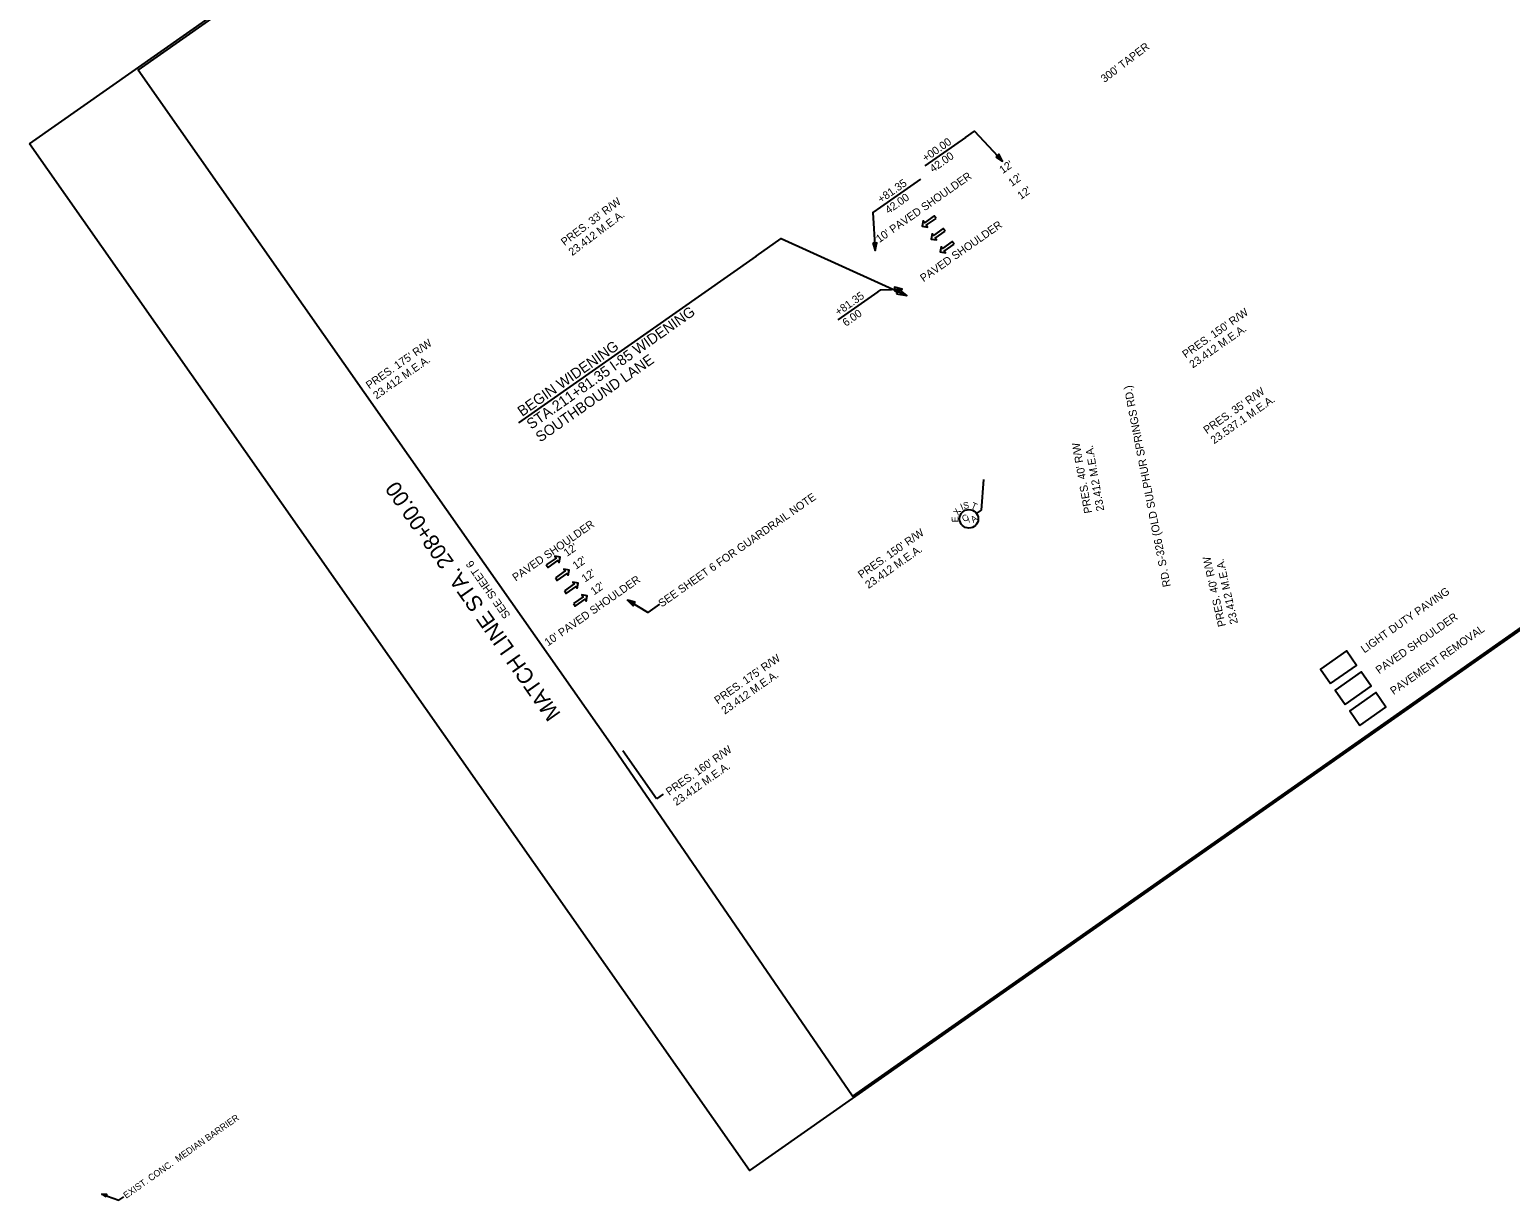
# Model space of a CAD drawing. Extents: x 1603735 to 1605655, y 1088656 to 1090462.
# Drawn here: x 1603735 to 1604864, y 1088656 to 1089549 of the extents above; entities that cross this region are included whole.
import ezdxf

# ---------------------------------------------------------------- set-up
doc = ezdxf.new("R2010")
doc.units = 0
for name, color, linetype in [('Copy of RD_HC_SUR_Bearing_TX200', 7, 'Continuous'), ('RD_DTM_BkLn1', 7, 'Continuous'), ('RD_EX_BldgApp', 7, 'Continuous'), ('RD_EX_Fence_Other', 7, 'Continuous'), ('RD_EX_Misc', 7, 'Continuous'), ('RD_EX_Misc_Golf_Teebox', 7, 'Continuous'), ('RD_EX_UT', 7, 'Continuous'), ('RD_EX_VEG', 7, 'Continuous'), ('RD_HC_SUR_CL400', 7, 'Continuous'), ('TR_PM_Yellow_Solid', 7, 'Continuous')]:
    doc.layers.add(name, color=color, linetype=linetype)

msp = doc.modelspace()

# ---------------------------------------------------------------- linework, layer by layer
at = {"layer": 'Copy of RD_HC_SUR_Bearing_TX200'}
msp.add_lwpolyline([(1604215.3, 1089110.4), (1604206.4, 1089104.2), (1604190.9, 1089113.5)], dxfattribs=at)
msp.add_lwpolyline([(1604196.7, 1089111.9), (1604190.9, 1089113.5), (1604195.1, 1089109.2)], close=True, dxfattribs=at)
at = {"layer": 'RD_DTM_BkLn1'}
msp.add_lwpolyline([(1603793, 1088658.5), (1603793.7, 1088660.2), (1603789.9, 1088660.6)], close=True, dxfattribs=at)
msp.add_lwpolyline([(1603789.9, 1088660.6), (1603802.9, 1088655.8), (1603806.7, 1088658.5)], dxfattribs=at)
at = {"layer": 'RD_EX_BldgApp'}
for p, q in [((1604213, 1088962), (1604187.4, 1088998.6)), ((1604218.1, 1088965.5), (1604213, 1088962))]:
    msp.add_line(p, q, dxfattribs=at)
at = {"layer": 'RD_EX_Fence_Other'}
msp.add_lwpolyline([(1603734.7, 1089461.6), (1605106, 1090423.5), (1605655.3, 1089640.4), (1604284, 1088678.5)], close=True, dxfattribs=at)
at = {"layer": 'RD_EX_Misc'}
for points in [[(1604426.2, 1089404.7), (1604424.8, 1089406.7), (1604417.3, 1089401.4), (1604416.4, 1089402.8), (1604415.7, 1089398.8), (1604419.6, 1089398.1), (1604418.7, 1089399.5)], [(1604433.1, 1089394.9), (1604431.7, 1089396.9), (1604424.2, 1089391.6), (1604423.3, 1089392.9), (1604422.6, 1089389), (1604426.5, 1089388.3), (1604425.6, 1089389.6)], [(1604440, 1089385.1), (1604438.6, 1089387), (1604431.1, 1089381.8), (1604430.1, 1089383.1), (1604429.5, 1089379.2), (1604433.4, 1089378.5), (1604432.5, 1089379.8)], [(1604128.9, 1089140.4), (1604130.3, 1089138.4), (1604137.8, 1089143.7), (1604138.7, 1089142.3), (1604139.4, 1089146.3), (1604135.5, 1089147), (1604136.4, 1089145.6)], [(1604135.8, 1089130.5), (1604137.2, 1089128.6), (1604144.7, 1089133.8), (1604145.6, 1089132.5), (1604146.3, 1089136.4), (1604142.4, 1089137.1), (1604143.3, 1089135.8)], [(1604142.7, 1089120.7), (1604144.1, 1089118.7), (1604151.6, 1089124), (1604152.5, 1089122.7), (1604153.2, 1089126.6), (1604149.2, 1089127.3), (1604150.2, 1089126)], [(1604149.6, 1089110.9), (1604150.9, 1089108.9), (1604158.5, 1089114.2), (1604159.4, 1089112.9), (1604160.1, 1089116.8), (1604156.1, 1089117.5), (1604157.1, 1089116.2)]]:
    msp.add_lwpolyline(points, close=True, dxfattribs=at)
at = {"layer": 'RD_EX_Misc_Golf_Teebox'}
for p, q in [((1604448.7, 1089466.5), (1604417.8, 1089444.9)), ((1604414.3, 1089434.7), (1604383.8, 1089413.3)), ((1604288.9, 1089376), (1604107.6, 1089248.8)), ((1604381.8, 1089348.8), (1604351.3, 1089327.4))]:
    msp.add_line(p, q, dxfattribs=at)
for points in [[(1604448.7, 1089466.5), (1604455.5, 1089471.3), (1604476.9, 1089448.4)], [(1604383.8, 1089413.3), (1604378.1, 1089409.3), (1604379.8, 1089380.2)], [(1604288.9, 1089376), (1604308.2, 1089389.5), (1604403.9, 1089345.9)], [(1604381.8, 1089348.8), (1604384, 1089350.3), (1604400.4, 1089350.8)], [(1604727.2, 1089049.9), (1604747.1, 1089063.8), (1604739.3, 1089074.8), (1604719.5, 1089060.9), (1604727.2, 1089049.9)], [(1604738.4, 1089034), (1604758.2, 1089047.9), (1604750.5, 1089058.9), (1604730.6, 1089045), (1604738.4, 1089034)], [(1604749.5, 1089018), (1604769.4, 1089032), (1604761.7, 1089043), (1604741.8, 1089029.1), (1604749.5, 1089018)]]:
    msp.add_lwpolyline(points, dxfattribs=at)
for points in [[(1604471.8, 1089451.6), (1604476.9, 1089448.4), (1604474.1, 1089453.7)], [(1604377.9, 1089385.9), (1604379.8, 1089380.2), (1604381, 1089386.1)], [(1604394.7, 1089349.1), (1604400.4, 1089350.8), (1604394.6, 1089352.2)], [(1604396, 1089347.2), (1604403.9, 1089345.9), (1604397.7, 1089351)], [(1604727.2, 1089049.9), (1604747.1, 1089063.8), (1604739.3, 1089074.8), (1604719.5, 1089060.9)], [(1604738.4, 1089034), (1604758.2, 1089047.9), (1604750.5, 1089058.9), (1604730.6, 1089045)], [(1604749.5, 1089018), (1604769.4, 1089032), (1604761.7, 1089043), (1604741.8, 1089029.1)]]:
    msp.add_lwpolyline(points, close=True, dxfattribs=at)
at = {"layer": 'RD_EX_UT'}
msp.add_lwpolyline([(1605233.6, 1090111), (1605405.8, 1089865.4), (1605593.1, 1089598.4), (1604362.4, 1088735.2), (1604177.8, 1089004.1), (1604005.5, 1089249.7), (1603817.5, 1089517.8), (1604919, 1090290.5), (1604939.8, 1090260.9), (1605067.4, 1090350.4)], close=True, dxfattribs=at)
msp.add_lwpolyline([(1605233.6, 1090111), (1605405.8, 1089865.4), (1605593.1, 1089598.4), (1604362.4, 1088735.2), (1604177.8, 1089004.1), (1604005.5, 1089249.7), (1603817.5, 1089517.8), (1604919, 1090290.5), (1604939.8, 1090260.9), (1605067.4, 1090350.4)], close=True, dxfattribs=at)
msp.add_lwpolyline([(1605233.6, 1090111), (1605405.8, 1089865.4), (1605593.1, 1089598.4), (1604362.4, 1088735.2), (1604177.8, 1089004.1), (1604005.5, 1089249.7), (1603817.5, 1089517.8), (1604919, 1090290.5), (1604939.8, 1090260.9), (1605067.4, 1090350.4)], close=True, dxfattribs=at)
at = {"layer": 'RD_EX_VEG'}
msp.add_lwpolyline([(1604177.8, 1089004.1), (1604091.7, 1089126.9), (1604005.5, 1089249.7)], dxfattribs=at)
at = {"layer": 'RD_HC_SUR_CL400'}
for p, q in [((1604460.8, 1089182.3), (1604462.8, 1089205.5)), ((1604457.1, 1089179.7), (1604460.8, 1089182.3))]:
    msp.add_line(p, q, dxfattribs=at)
msp.add_circle((1604451.3, 1089175.6), 7.08, dxfattribs=at)

# ---------------------------------------------------------------- texts
at = {"layer": 'Copy of RD_HC_SUR_Bearing_TX200'}
msp.add_text('SEE SHEET 6 FOR GUARDRAIL NOTE', height=6, rotation=35.0468, dxfattribs=at).set_placement((1604217, 1089107.9))
at = {"layer": 'RD_DTM_BkLn1'}
msp.add_text('EXIST. CONC.  MEDIAN BARRIER', height=5, rotation=35.0535, dxfattribs=at).set_placement((1603808.4, 1088656.9))
at = {"layer": 'RD_EX_BldgApp'}
for s, rotation, p in [("PRES. 33' R/W", 37.0371, (1604142.9, 1089383.5)), ('23.412 M.E.A.', 37.0371, (1604148.7, 1089375.9)), ("PRES. 150' R/W", 35.0468, (1604616.7, 1089297.9)), ('23.412 M.E.A.', 35.0468, (1604622.1, 1089290.2)), ("PRES. 175' R/W", 35.0468, (1603993.9, 1089274.3)), ('23.412 M.E.A.', 35.0468, (1603999.4, 1089266.5)), ("PRES. 35' R/W", 35.0468, (1604632.8, 1089240.1)), ('23.537.1 M.E.A.', 35.0468, (1604638.3, 1089232.4)), ("PRES. 40' R/W", 100.0806, (1604545.3, 1089180.3)), ('23.412 M.E.A.', 100.0806, (1604554.6, 1089182)), ("PRES. 150' R/W", 35.0468, (1604369.3, 1089129.8)), ('23.412 M.E.A.', 35.0468, (1604374.7, 1089122)), ("PRES. 40' R/W", 102.6737, (1604647.4, 1089094)), ('23.412 M.E.A.', 102.6737, (1604656.6, 1089096)), ("PRES. 175' R/W", 35.0468, (1604259.7, 1089034)), ('23.412 M.E.A.', 35.0468, (1604265.1, 1089026.2)), ("PRES. 160' R/W", 35.0468, (1604222.7, 1088964.3)), ('23.412 M.E.A.', 35.0468, (1604228.2, 1088956.5))]:
    msp.add_text(s, height=6, rotation=rotation, dxfattribs=at).set_placement(p)
at = {"layer": 'RD_EX_Misc_Golf_Teebox'}
for s, height, rotation, p in [("300' TAPER", 6, 37.3374, (1604554.7, 1089508)), ('+00.00', 6, 35.0468, (1604418.3, 1089447.6)), ('42.00', 6, 35.0468, (1604424, 1089439.5)), ("12'", 6, 35.0436, (1604477.1, 1089438.5)), ("10' PAVED SHOULDER", 6, 35.0452, (1604383, 1089385.9)), ('+81.35', 6, 35.0468, (1604384.3, 1089416.1)), ("12'", 6, 35.0436, (1604484, 1089428.7)), ("12'", 6, 35.0436, (1604490.9, 1089418.8)), ('42.00', 6, 35.0468, (1604390, 1089407.9)), ('PAVED SHOULDER', 6, 35.0452, (1604416.7, 1089356)), ('+81.35', 6, 35.0468, (1604351.8, 1089330.2)), ('STA.211+81.35 I-85 WIDENING', 8, 35.0485, (1604117.4, 1089243.5)), ('6.00', 6, 35.0468, (1604357.5, 1089322)), ('BEGIN WIDENING', 8, 35.0485, (1604110.5, 1089253.3)), ('SOUTHBOUND LANE', 8, 35.0485, (1604124.3, 1089233.7)), ('PAVED SHOULDER', 6, 35.0452, (1604105.6, 1089127.7)), ("12'", 6, 35.0436, (1604144.7, 1089146.5)), ("12'", 6, 35.0436, (1604151.6, 1089136.7)), ("12'", 6, 35.0436, (1604158.4, 1089126.9)), ("10' PAVED SHOULDER", 6, 35.0452, (1604130.2, 1089078.2)), ("12'", 6, 35.0436, (1604165.3, 1089117.1)), ('LIGHT DUTY PAVING', 6, 35.0468, (1604753, 1089072.9)), ('PAVED SHOULDER', 6, 35.0468, (1604764.2, 1089057)), ('PAVEMENT REMOVAL', 6, 35.0468, (1604775.3, 1089041.1))]:
    msp.add_text(s, height=height, rotation=rotation, dxfattribs=at).set_placement(p)
at = {"layer": 'RD_EX_VEG'}
for s, height, rotation, p in [('MATCH LINE STA. 208+00.00', 12, 125.0468, (1604140.3, 1089026.8)), ('SEE SHEET 6', 6, 125.0981, (1604101.8, 1089102.1))]:
    msp.add_text(s, height=height, rotation=rotation, dxfattribs=at).set_placement(p)
at = {"layer": 'RD_HC_SUR_CL400'}
for s, rotation, p in [('X', 58.1882, (1604443.2, 1089177.8)), ('I', 23.0267, (1604446, 1089182.1)), ('S', 11.3062, (1604447.4, 1089183)), ('T', 336.1448, (1604452.4, 1089183.9)), ('E', 91.6753, (1604443.3, 1089173)), ('C', 35.0436, (1604448, 1089172.8)), ('/', 35.0436, (1604451.6, 1089172.7)), ('A', 35.0436, (1604454.7, 1089172.3))]:
    msp.add_text(s, height=5, rotation=rotation, dxfattribs=at).set_placement(p)
at = {"layer": 'TR_PM_Yellow_Solid'}
msp.add_text('RD. S-326 (OLD SULPHUR SPRINGS RD.)', height=6, rotation=101.1077, dxfattribs=at).set_placement((1604605.3, 1089124.2))

doc.saveas('drawing.dxf')
